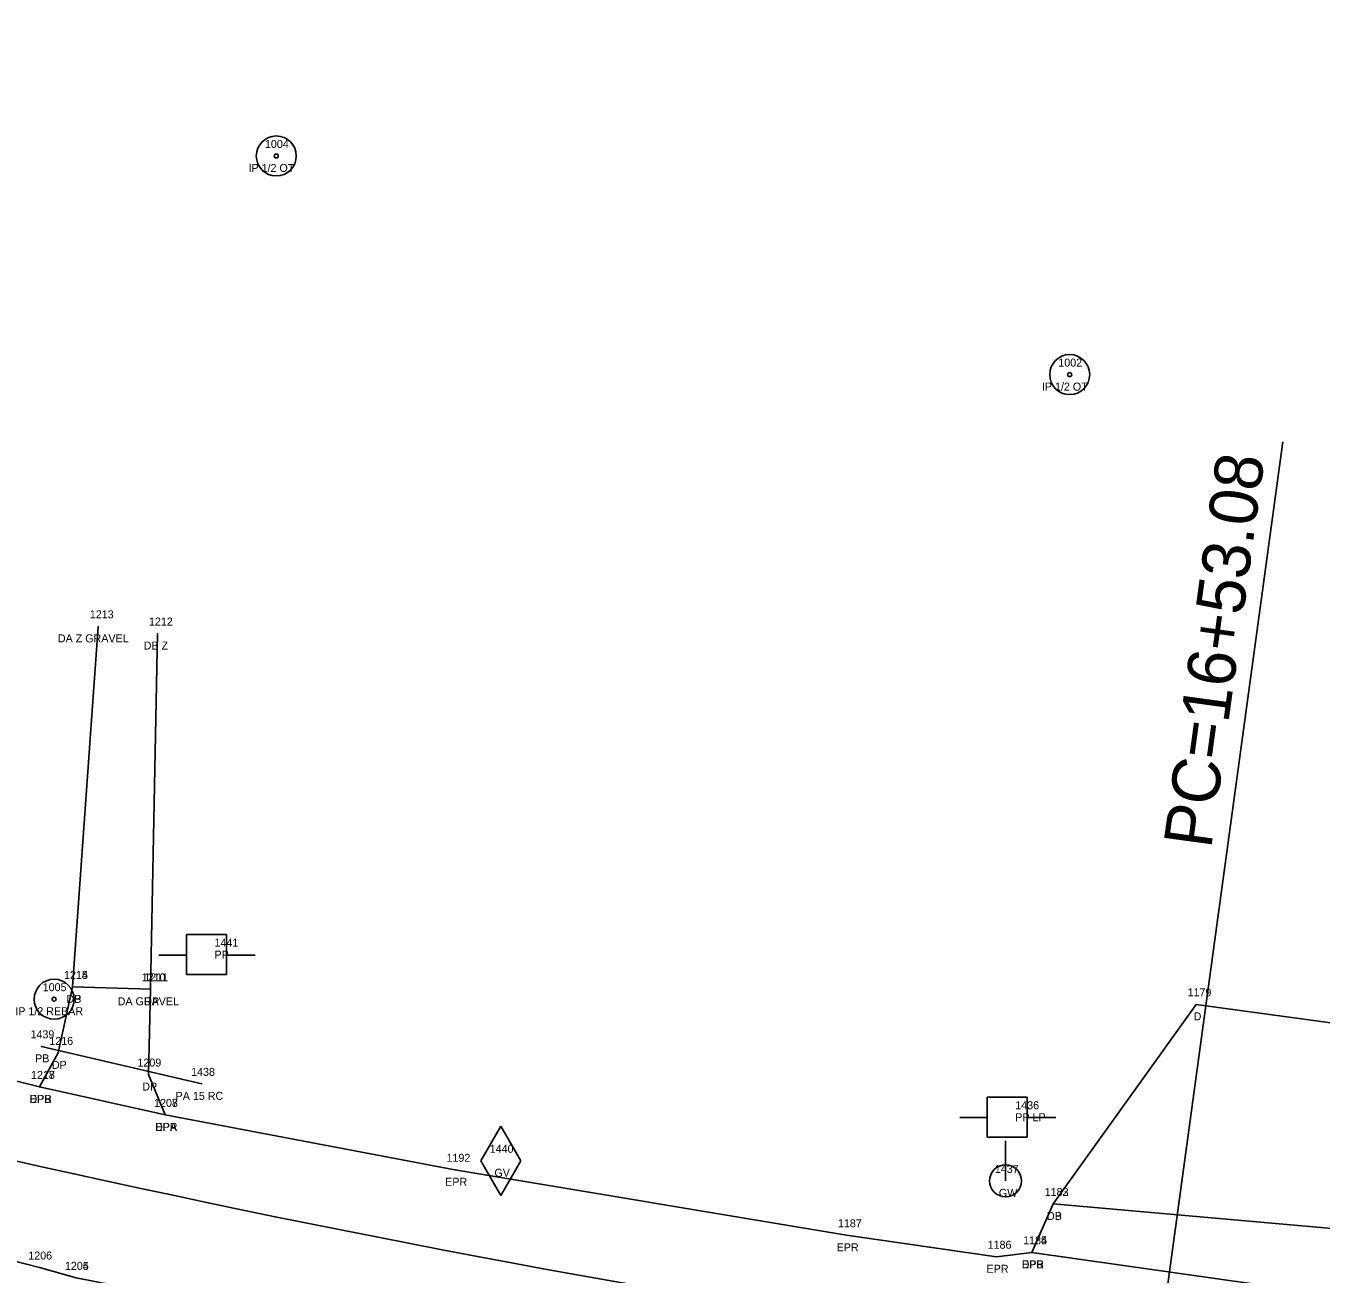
# Model space of a CAD drawing. Extents: x 1812340 to 1815011, y 1177659 to 1180159.
# Drawn here: x 1813396.9 to 1813558.8, y 1178783 to 1178939 of the extents above; entities that cross this region are included whole.
import ezdxf

# ---------------------------------------------------------------- set-up
doc = ezdxf.new("R2010")
doc.units = 0
for name, color, linetype in [('RD_EX_DR_Pipe', 7, 'Continuous'), ('RD_EX_DR_Pipe_txCode', 7, 'Continuous'), ('RD_EX_Driveway', 7, 'Continuous'), ('RD_EX_Driveway_txCode', 7, 'Continuous'), ('RD_EX_DV_Prop_txCode', 7, 'Continuous'), ('RD_EX_DV_PropPin', 7, 'Continuous'), ('RD_EX_Road', 7, 'Continuous'), ('RD_EX_Road_txCode', 7, 'Continuous'), ('RD_EX_UT', 7, 'Continuous'), ('RD_EX_UT_txCode', 7, 'Continuous'), ('RD_HC_CL', 7, 'Continuous'), ('RD_HC_Data', 7, 'Continuous'), ('RD_SMD_Locator', 7, 'Continuous')]:
    doc.layers.add(name, color=color, linetype=linetype)

msp = doc.modelspace()

# ---------------------------------------------------------------- linework, layer by layer
at = {"layer": 'RD_EX_DR_Pipe'}
msp.add_line((1813418.94, 1178806.8), (1813398.87, 1178811.49), dxfattribs=at)
at = {"layer": 'RD_EX_Driveway'}
for p, q in [((1813405.99, 1178863.99), (1813402.78, 1178818.92)), ((1813412.51, 1178818.62), (1813413.38, 1178863.09))]:
    msp.add_line(p, q, dxfattribs=at)
for points in [[(1813414.35, 1178802.92), (1813412.27, 1178807.96), (1813412.51, 1178818.62), (1813402.78, 1178818.92), (1813400.96, 1178810.67), (1813398.64, 1178806.42)], [(1813613.34, 1178784.52), (1813617.78, 1178806.55), (1813543.17, 1178816.74), (1813525.31, 1178791.79)], [(1813638.42, 1178791.25), (1813630.13, 1178786.38), (1813613.34, 1178784.52), (1813588.43, 1178786.24), (1813525.31, 1178791.79), (1813522.62, 1178785.74)]]:
    msp.add_lwpolyline(points, dxfattribs=at)
at = {"layer": 'RD_EX_DV_PropPin'}
for centre, radius in [((1813428.23, 1178922.79), 2.5), ((1813428.23, 1178922.79), 0.25), ((1813527.37, 1178895.46), 2.5), ((1813527.37, 1178895.46), 0.25), ((1813400.47, 1178817.38), 2.5), ((1813400.47, 1178817.38), 0.25)]:
    msp.add_circle(centre, radius, dxfattribs=at)
at = {"layer": 'RD_EX_Road'}
for points in [[(1813668.47, 1179045.78), (1813666.19, 1178996.77), (1813663.63, 1178947.81), (1813660.91, 1178900.64), (1813659.53, 1178882.12), (1813657.19, 1178859.48), (1813656.91, 1178851.42), (1813653.67, 1178829.82), (1813648.43, 1178809.53), (1813642.94, 1178796.31), (1813638.42, 1178791.25), (1813631.39, 1178785.04), (1813613.59, 1178777.71), (1813596.09, 1178775.31), (1813522.62, 1178785.74), (1813518.21, 1178785.19), (1813499.47, 1178787.87), (1813450.56, 1178796.06), (1813414.35, 1178802.92), (1813398.64, 1178806.42), (1813355.44, 1178817.13)], [(1813732.94, 1178707.95), (1813689.88, 1178731.75), (1813641.71, 1178744.36), (1813593.37, 1178752.09), (1813544.49, 1178758.77), (1813495.45, 1178766.29), (1813446.8, 1178774.66), (1813426.54, 1178777.95), (1813403.21, 1178782.55), (1813398.65, 1178783.84), (1813350.68, 1178796.09), (1813343.23, 1178797.92), (1813318.7, 1178804.23), (1813303.26, 1178808.85), (1813256.8, 1178823.17), (1813209.81, 1178838.91), (1813163.27, 1178855.57)]]:
    msp.add_lwpolyline(points, dxfattribs=at)
at = {"layer": 'RD_EX_UT'}
for p, q in [((1813422, 1178825.46), (1813417, 1178825.46)), ((1813417, 1178825.46), (1813417, 1178820.46)), ((1813422, 1178820.46), (1813422, 1178825.46)), ((1813413.57, 1178822.89), (1813417.04, 1178822.89)), ((1813421.93, 1178822.89), (1813425.57, 1178822.89)), ((1813417, 1178820.46), (1813422, 1178820.46)), ((1813522.06, 1178805.14), (1813517.06, 1178805.14)), ((1813517.06, 1178805.14), (1813517.06, 1178800.14)), ((1813522.06, 1178800.14), (1813522.06, 1178805.14)), ((1813453.78, 1178797.19), (1813456.28, 1178801.52)), ((1813456.28, 1178801.52), (1813458.78, 1178797.19)), ((1813513.63, 1178802.58), (1813517.1, 1178802.58)), ((1813521.99, 1178802.58), (1813525.63, 1178802.58)), ((1813517.06, 1178800.14), (1813522.06, 1178800.14)), ((1813519.36, 1178794.67), (1813519.36, 1178799.67)), ((1813453.78, 1178797.19), (1813456.28, 1178792.86)), ((1813456.28, 1178792.86), (1813458.78, 1178797.19))]:
    msp.add_line(p, q, dxfattribs=at)
msp.add_circle((1813519.36, 1178794.67), 2, dxfattribs=at)
at = {"layer": 'RD_HC_CL'}
msp.add_arc((1813766.93, 1180445.18), 1689.31, 243.58271, 262.2191, dxfattribs=at)
at = {"layer": 'RD_HC_Data'}
msp.add_line((1813538.22, 1178771.42), (1813554.02, 1178887.04), dxfattribs=at)
at = {"layer": 'RD_SMD_Locator'}
for centre in [(1813405.99, 1178863.99), (1813413.38, 1178863.09), (1813402.78, 1178818.92), (1813402.78, 1178818.92), (1813412.51, 1178818.62), (1813412.51, 1178818.62), (1813543.17, 1178816.74), (1813398.87, 1178811.49), (1813400.96, 1178810.67), (1813412.27, 1178807.96), (1813398.64, 1178806.42), (1813398.64, 1178806.42), (1813418.94, 1178806.8), (1813414.35, 1178802.92), (1813414.35, 1178802.92), (1813450.56, 1178796.06), (1813525.31, 1178791.79), (1813525.31, 1178791.79), (1813499.47, 1178787.87), (1813518.21, 1178785.19), (1813522.62, 1178785.74), (1813522.62, 1178785.74), (1813398.65, 1178783.84)]:
    msp.add_circle(centre, 0.001, dxfattribs=at)

# ---------------------------------------------------------------- texts
at = {"layer": 'RD_EX_DR_Pipe_txCode'}
for s, p in [('1439', (1813397.52, 1178812.49)), ('PB', (1813398.09, 1178809.49)), ('1438', (1813417.59, 1178807.8)), ('PA 15 RC', (1813415.65, 1178804.8))]:
    msp.add_text(s, height=1, dxfattribs=at).set_placement(p)
at = {"layer": 'RD_EX_Driveway_txCode'}
for s, p in [('1213', (1813404.93, 1178864.99)), ('1212', (1813412.32, 1178864.09)), ('DA Z GRAVEL', (1813400.94, 1178861.99)), ('DB Z', (1813411.66, 1178861.09)), ('1214', (1813401.71, 1178819.92)), ('1215', (1813401.71, 1178819.92)), ('1210', (1813411.41, 1178819.62)), ('1211', (1813411.73, 1178819.62)), ('DB', (1813402, 1178816.92)), ('DP', (1813402, 1178816.92)), ('DA GRAVEL', (1813408.41, 1178816.62)), ('DP', (1813411.73, 1178816.62)), ('1179', (1813542.1, 1178817.74)), ('D', (1813542.86, 1178814.74)), ('1216', (1813399.87, 1178811.67)), ('DP', (1813400.18, 1178808.67)), ('1209', (1813410.88, 1178808.96)), ('1217', (1813397.58, 1178807.42)), ('DP', (1813411.49, 1178805.96)), ('DPB', (1813397.39, 1178804.42)), ('1208', (1813412.96, 1178803.92)), ('DPA', (1813413.08, 1178800.92)), ('1182', (1813524.25, 1178792.79)), ('1183', (1813524.25, 1178792.79)), ('DP', (1813524.53, 1178789.79)), ('DB', (1813524.53, 1178789.79)), ('1184', (1813521.56, 1178786.74)), ('1204', (1813401.82, 1178783.55)), ('DPB', (1813521.37, 1178783.74))]:
    msp.add_text(s, height=1, dxfattribs=at).set_placement(p)
at = {"layer": 'RD_EX_DV_Prop_txCode'}
for s, p in [('1004', (1813426.81, 1178923.79)), ('IP 1/2 OT', (1813424.76, 1178920.79)), ('1002', (1813525.95, 1178896.46)), ('IP 1/2 OT', (1813523.9, 1178893.46)), ('1005', (1813399.04, 1178818.38)), ('IP 1/2 REBAR', (1813395.62, 1178815.38))]:
    msp.add_text(s, height=1, dxfattribs=at).set_placement(p)
at = {"layer": 'RD_EX_Road_txCode'}
for s, p in [('1218', (1813397.58, 1178807.42)), ('EPR', (1813397.42, 1178804.42)), ('1207', (1813412.96, 1178803.92)), ('EPR', (1813413.12, 1178800.92)), ('1192', (1813449.5, 1178797.06)), ('EPR', (1813449.33, 1178794.06)), ('1187', (1813498.41, 1178788.87)), ('EPR', (1813498.25, 1178785.87)), ('1186', (1813517.12, 1178786.19)), ('1185', (1813521.56, 1178786.74)), ('1206', (1813397.24, 1178784.84)), ('1205', (1813401.82, 1178783.55)), ('EPR', (1813516.98, 1178783.19)), ('EPR', (1813521.39, 1178783.74))]:
    msp.add_text(s, height=1, dxfattribs=at).set_placement(p)
at = {"layer": 'RD_EX_UT_txCode'}
for s, p in [('1441', (1813420.51, 1178823.95)), ('PP', (1813420.51, 1178822.45)), ('1436', (1813520.57, 1178803.63)), ('PP LP', (1813520.57, 1178802.13)), ('1440', (1813454.9, 1178798.19)), ('GV', (1813455.49, 1178795.19)), ('1437', (1813518.02, 1178795.67)), ('GW', (1813518.52, 1178792.67))]:
    msp.add_text(s, height=1, dxfattribs=at).set_placement(p)
at = {"layer": 'RD_HC_Data'}
msp.add_text('PC=16+53.08', height=6, rotation=82.2191, dxfattribs=at).set_placement((1813545.04, 1178836.09))

doc.saveas('drawing.dxf')
